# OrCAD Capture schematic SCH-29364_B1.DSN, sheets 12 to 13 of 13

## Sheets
12 X-02 IOMUX
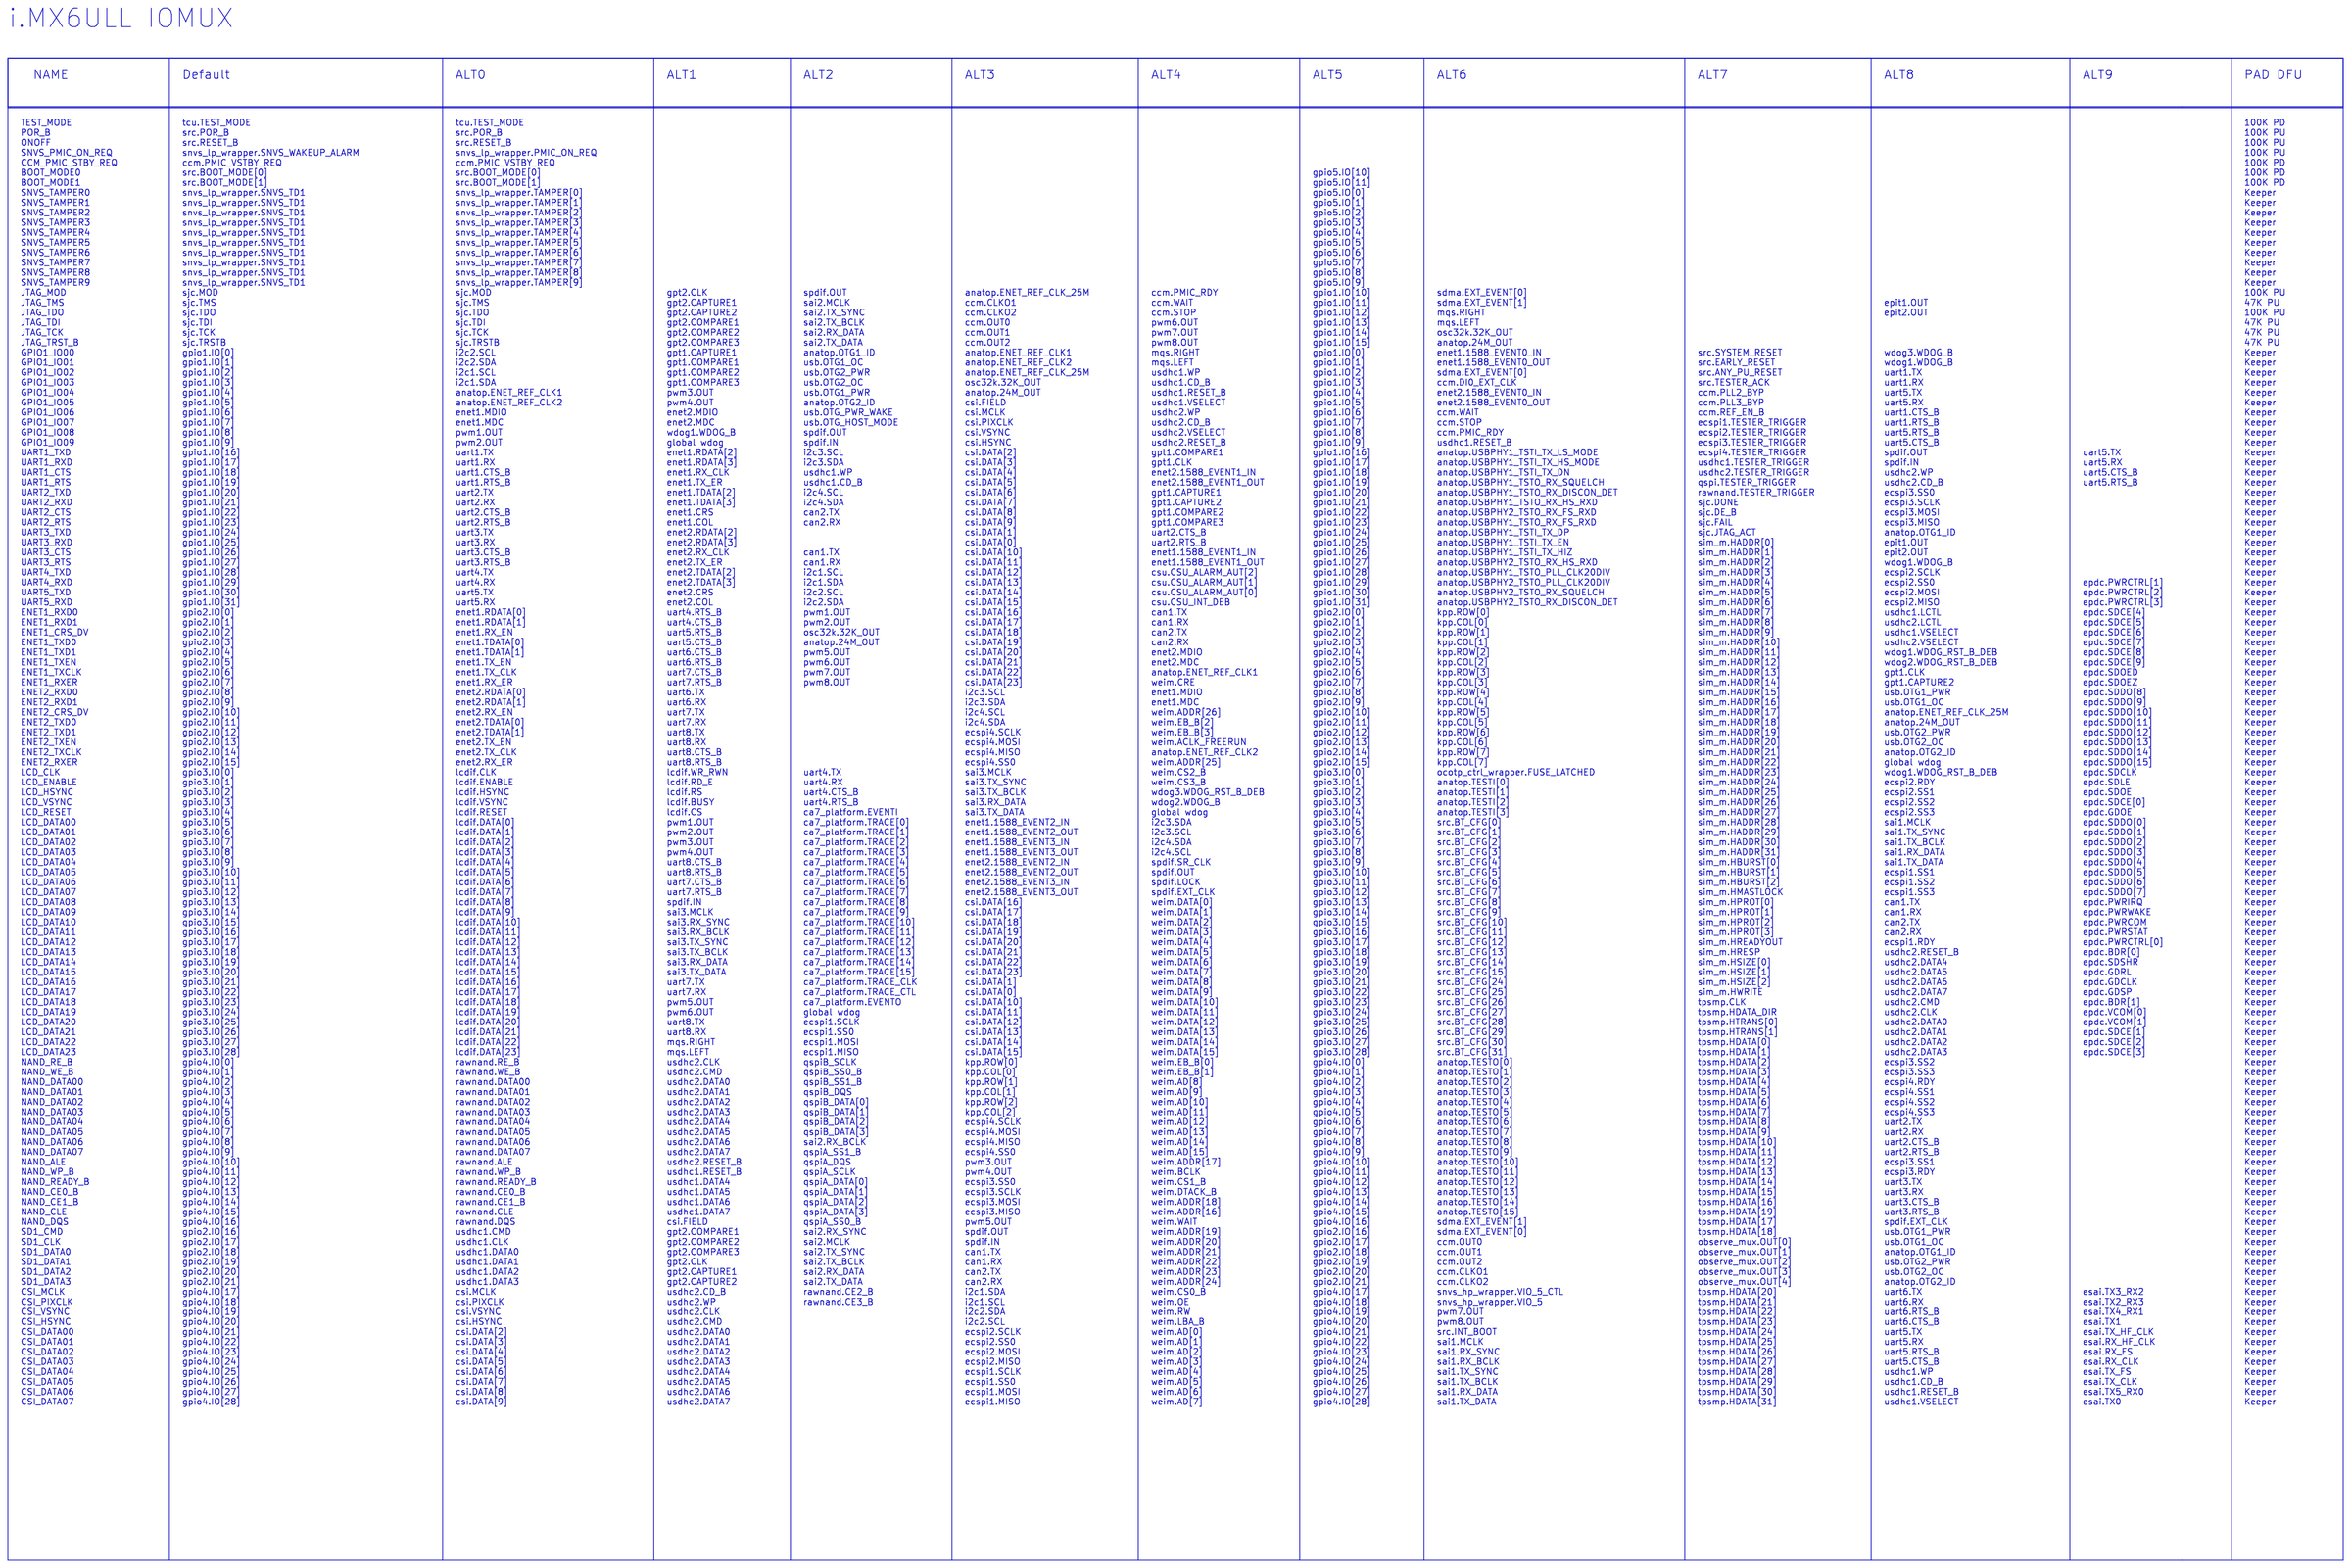
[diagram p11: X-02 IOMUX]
13 C-03 eMMC/NAND/TF/QSPI: size C
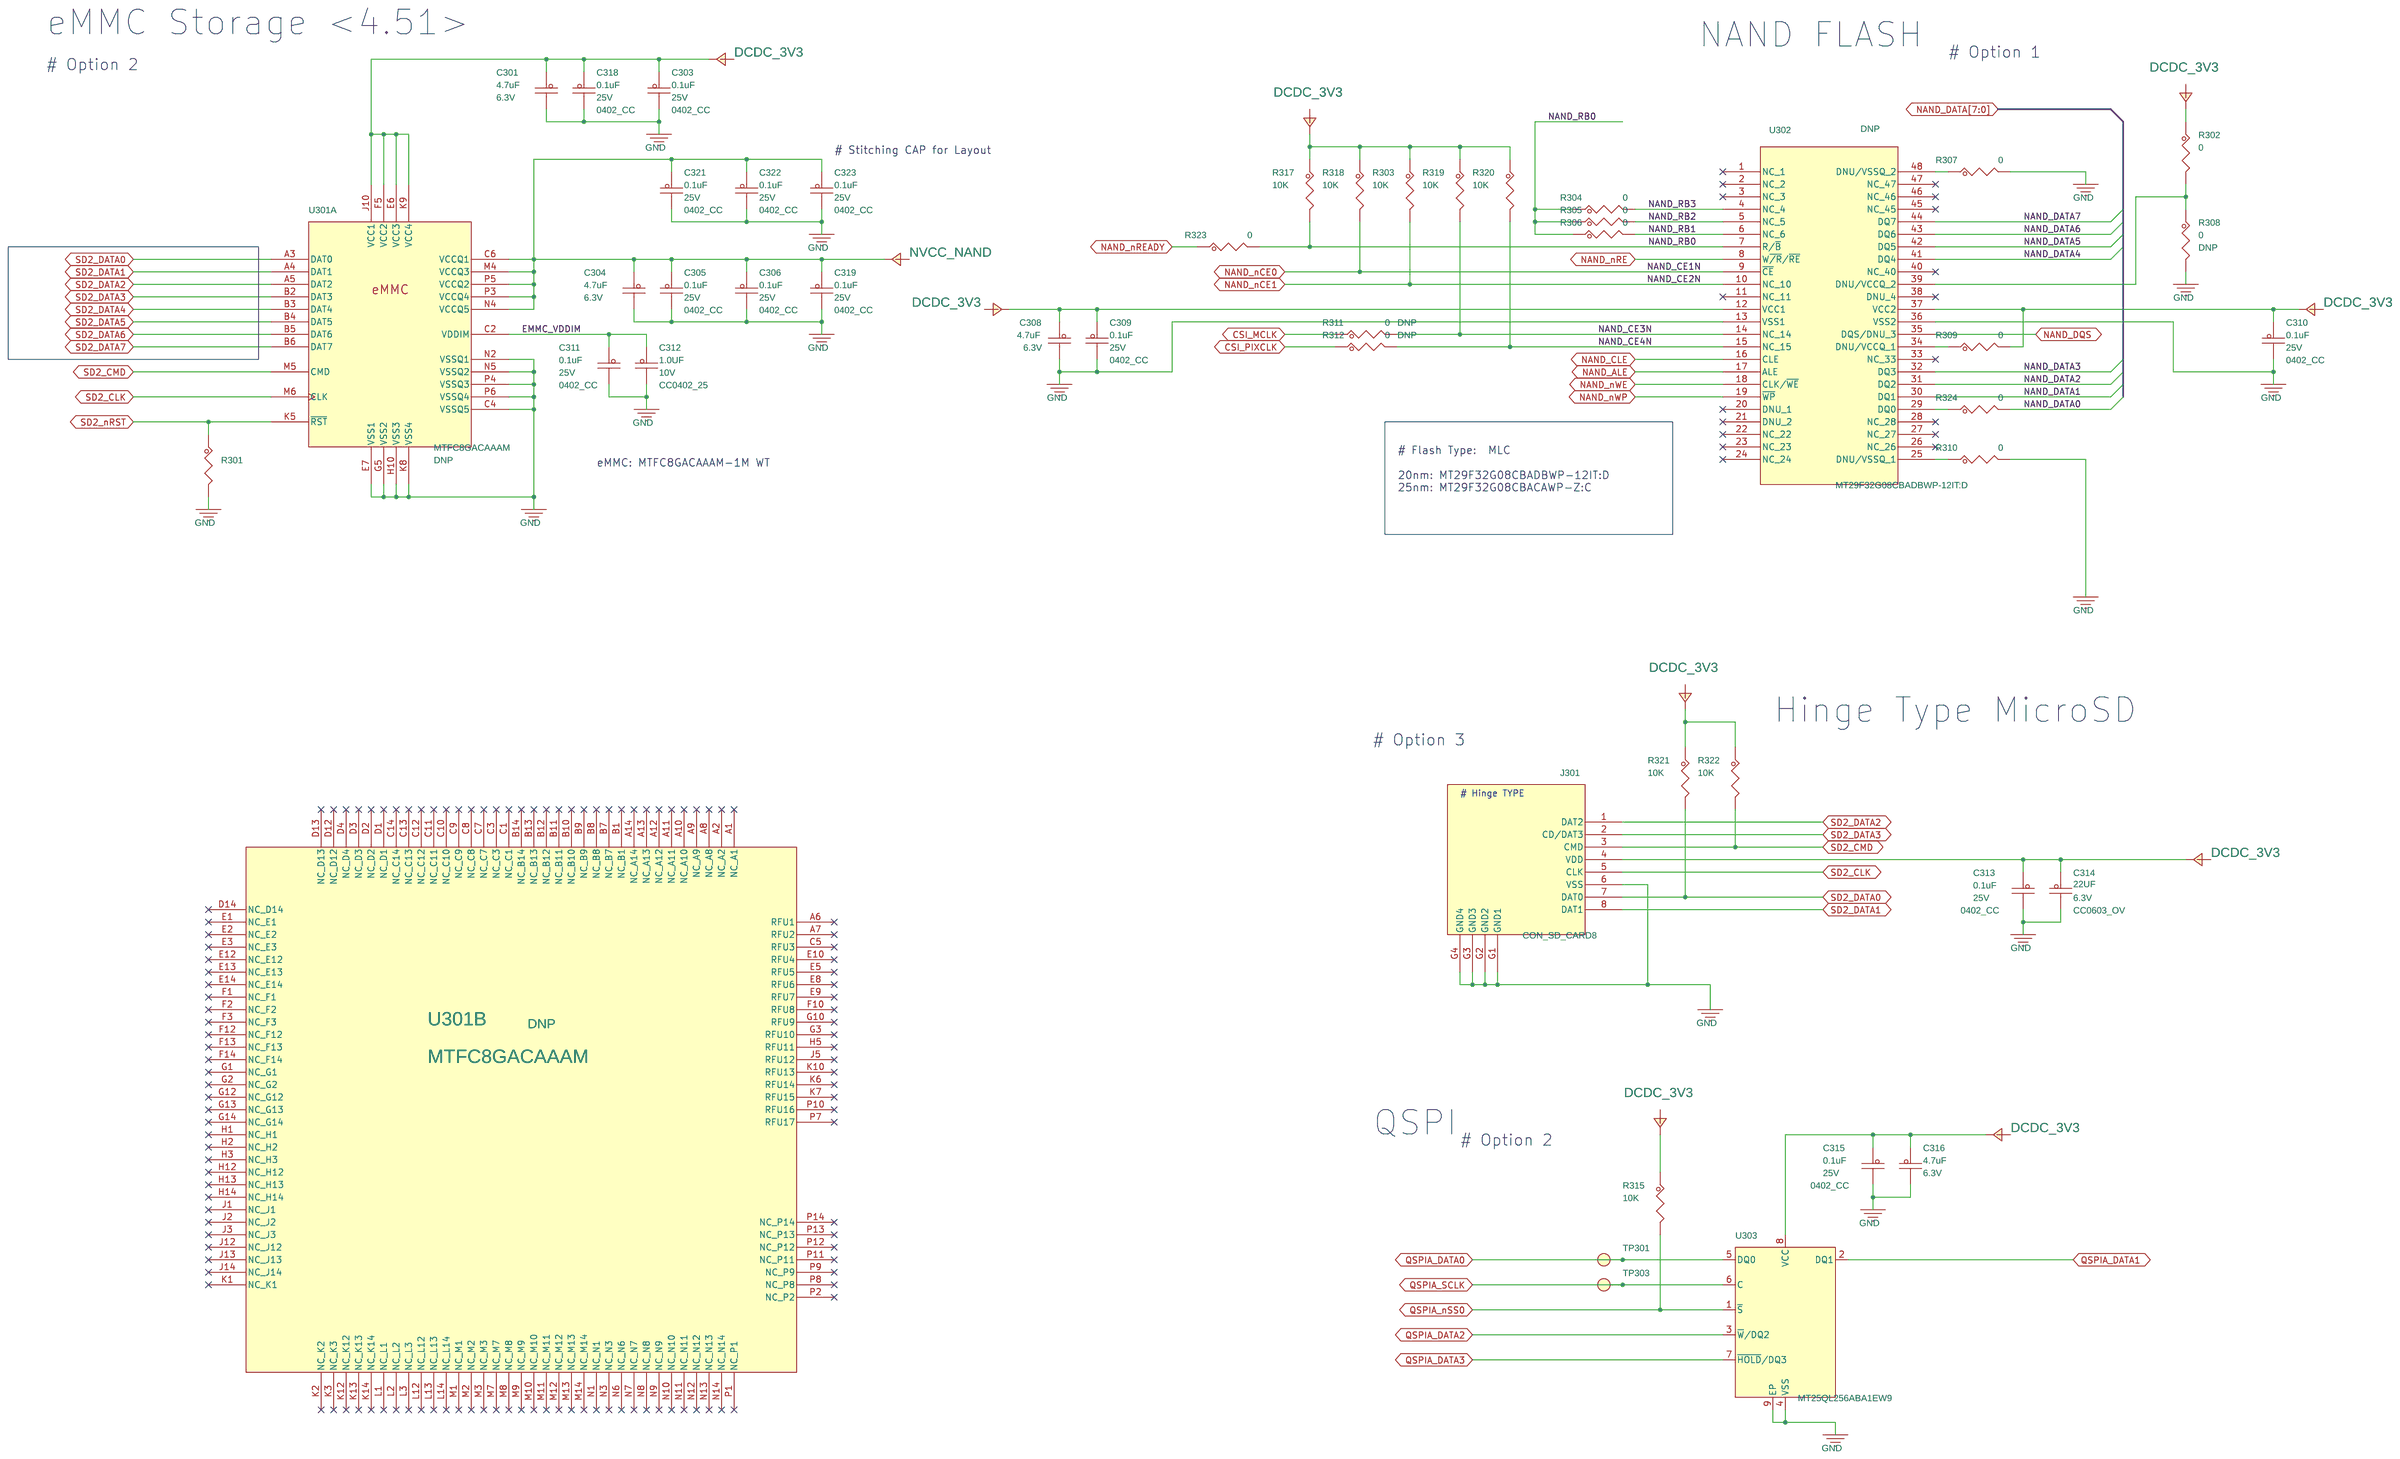
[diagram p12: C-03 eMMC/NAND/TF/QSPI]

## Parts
C301  4.7uF  [cc0402_tol0p15]
C303  0.1uF  [0402_CC]
C304  4.7uF  [cc0402_tol0p15]
C305  0.1uF  [0402_CC]
C306  0.1uF  [0402_CC]
C308  4.7uF  [cc0402_tol0p15]
C309  0.1uF  [0402_CC]
C310  0.1uF  [0402_CC]
C311  0.1uF  [0402_CC]
C312  1.0UF  [CC0402_25]
C313  0.1uF  [0402_CC]
C314  22UF  [CC0603_OV]
C315  0.1uF  [0402_CC]
C316  4.7uF  [cc0402_tol0p15]
C318  0.1uF  [0402_CC]
C319  0.1uF  [0402_CC]
C321  0.1uF  [0402_CC]
C322  0.1uF  [0402_CC]
C323  0.1uF  [0402_CC]
J301  CON_SD_CARD8  [con8_microsd_1p1_smt]
R301  10K  [0402_CC]
R302  0  [0402_CC]
R303  10K  [0402_CC]
R304  0  [0402_CC]
R305  0  [0402_CC]
R306  0  [0402_CC]
R307  0  [0402_CC]
R308  0  [0402_CC]
R309  0  [0402_CC]
R310  0  [0402_CC]
R311  0  [0402_CC]
R312  0  [0402_CC]
R315  10K  [0402_CC]
R317  10K  [0402_CC]
R318  10K  [0402_CC]
R319  10K  [0402_CC]
R320  10K  [0402_CC]
R321  10K  [0402_CC]
R322  10K  [0402_CC]
R323  0  [0402_CC]
R324  0  [0402_CC]
TP301  TP_35MIL  [testpoint_35mil]
TP303  TP_35MIL  [testpoint_35mil]
U301  MTFC8GACAAAM  [FBGA153_0P5_11P5X13]  (sections A,B)
U302  MT29F32G08CBADBWP-12IT:D  [tsop48_12x20]
U303  MT25QL256ABA1EW9  [wpdfn8_1p27_8x6mm]

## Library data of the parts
C301 C304 C308 C316 = CAP_NP: CAP CER 4.7UF 6.3V 20% X5R 0402; AGILE_PN: 150-78463; CAD_APPROVED: Yes; FPLIST: CC0402_25,CC0402_HD,0402_CC; HEIGHT: 0.65MM; MFG_NAME01: TDK; MFG_PN01: C1005X5R0J475M; ROHS: Yes; Rated Voltage: 6.3V; Temp Range: -55C to +85C; Tolerance: 20%; VOLTAGE: 6.3V; voltage rating: 6.3V
C303 C305 C306 C309-C311 C313 C315 C318 C319 C321-C323 = CAP_NP: CAP CER 0.1UF 25V 10% X5R 0402; AGILE_PN: 150-78633; CAD_APPROVED: Yes; FPLIST: CC0402_25,CC0402_HD,0402_CC; HEIGHT: 0.55MM; MFG_NAME01: YAGEO AMERICA; MFG_PN01: CC0402KRX5R8BB104; Package Size: 0402; ROHS: Yes; Rated Voltage: 25V; Temp Range: -55C to +85C; Tolerance: 10%; VOLTAGE: 25V
C312 = CAP_NP: CAP CER 1.0UF 10V 10% X5R 0402; AGILE_PN: 150-75772; CAD_APPROVED: Yes; FPLIST: CC0402_25,CC0402_HD,0402_CC; HEIGHT: 0.6MM; MFG_NAME01: YAGEO AMERICA; MFG_PN01: CC0402KRX5R6BB105; Package Size: 0402; ROHS: Yes; Rated Voltage: 10V; Temp Range: -55C to +85C; Tolerance: 10%; VOLTAGE: 10V
C314 = CAP_NP: CAP CER 22UF 6.3V 20% X5R 0603; AGILE_PN: 150-78467; CAD_APPROVED: Yes; FPLIST: CC0603_OV,CC0603,0603_CC; HEIGHT: 1MM; MFG_NAME01: SAMSUNG; MFG_PN01: CL10A226MQ8NRNE; Package Size: 0603; ROHS: Yes; Rated Voltage: 6.3V; Temp Range: -55C to +85C; Tolerance: 20%; VOLTAGE: 6.3V; voltage rating: 6.3V
J301 = CON_MICROSD_8P_4G: CON 8 MICRO SD CARD HINGED TYPE SMT 1.1MM SP 81H AU; 3D_Mechanical_Footprint_File: http://fcl.am.freescale.net/ALLEGRO/step/con8_microsd_1p1_smt.STEP; AGILE_PN: 211-81952; CAD_APPROVED: Yes; Contact Voltage: 100 V DC; HEIGHT: 2.05MM; MFG_NAME01: MOLEX; MFG_PN01: 472192001; Package Type: SMD/SMT; ROHS: Yes; Temp Range: -40°C to +85°C
R301 = RES: RES MF 10K 1/16W 5% 0402; AGILE_PN: 470-75557; CAD_APPROVED: Yes; FPLIST: RC0402_25,RC0402_HD,0402_CC; HEIGHT: 0.4 MM; MFG_NAME01: BOURNS; MFG_PN01: CR0402-JW-103GLF; ROHS: Yes; TOL: 5%; Tolerance: 5%
R302 R304-R307 R309 R310 R323 R324 = RES: RES MF ZERO OHM 1/16W 5% 0402; AGILE_PN: 470-75394; CAD_APPROVED: Yes; FPLIST: RC0402_25,RC0402_HD,RC0402_X2,0402_CC; HEIGHT: 0.45 MM; MFG_NAME01: YAGEO AMERICA; MFG_PN01: RC0402JR-070RL; ROHS: Yes; Temp Range: -55 to +155C; Tolerance: 5%
R303 R315 R317-R322 = RES: RES MF 10K 1/16W 5% 0402; AGILE_PN: 470-75557; CAD_APPROVED: Yes; FPLIST: RC0402_25,RC0402_HD,0402_CC; HEIGHT: 0.4 MM; MFG_NAME01: BOURNS; MFG_PN01: CR0402-JW-103GLF; ROHS: Yes; Tolerance: 5%
R308 R311 R312 = RES: RES MF ZERO OHM 1/16W 5% 0402; AGILE_PN: 470-75394; ASSY_OPT: DNP; CAD_APPROVED: Yes; FPLIST: RC0402_25,RC0402_HD,RC0402_X2,0402_CC; HEIGHT: 0.45 MM; MFG_NAME01: YAGEO AMERICA; MFG_PN01: RC0402JR-070RL; ROHS: Yes; Temp Range: -55 to +155C; Tolerance: 5%
TP301 TP303 = T_POINT_R: TEST POINT PAD .035 SMT, no part to order; AGILE_PN: 510-75618; CAD_APPROVED: Yes; HEIGHT: 0.1MM; ROHS: Yes
U301 = MTFC4GMVEA_WFBGA_153P: IC MEM NAND FLASH 8GB MMC 4.51 CTLR 2.7-3.6V FBGA153; AGILE_PN: 342-00603; ASSY_OPT: DNP; CAD_APPROVED: Yes; HEIGHT: 1.165 MM; MFG_NAME01: MICRON; MFG_PN01: MTFC8GACAAAM-1M WT; ROHS: Yes; VOLTAGE: 2.7¨C3.6V
U302 = MT29F32G08CBADB_48P: OBSOLETE IC MEM NAND FLASH ASYNC 32GB 2.7-3.6V TSOP48. No Suggested Replacement.; AGILE_PN: 334-77617; ASSY_OPT: DNP; CAD_APPROVED: Yes; HEIGHT: 1.2 MM; MFG_NAME01: MICRON; ROHS: Yes; VOLTAGE: 2.7-3.6V
U303 = MT25QL256ABA1EW9_9P: IC MEM FLASH SERIAL NOR 256MBIT 2.7-3.6V MLP8; AGILE_PN: 334-77609; CAD_APPROVED: Yes; HEIGHT: 0.8MM; MFG_NAME01: MICRON; MFG_PN01: MT25QL256ABA1EW9-0SIT; ROHS: Yes; VOLTAGE: 2.7-3.6V

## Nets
GND: C301.2 C303.2 C304.2 C305.2 C306.2 C308.2 C309.2 C310.2 C311.2 C312.2 C313.2 C314.2 C315.2 C316.2 C318.2 C319.2 C321.2 C322.2 C323.2 J301.6(VSS) J301.G1(GND1) J301.G2(GND2) J301.G3(GND3) J301.G4(GND4) R301.2 R307.2 R308.2 R310.2 U301.C4(VSSQ5) U301.E7(VSS1) U301.G5(VSS2) U301.H10(VSS3) U301.K8(VSS4) U301.N2(VSSQ1) U301.N5(VSSQ2) U301.P4(VSSQ3) U301.P6(VSSQ4) U302.13(VSS1) U302.36(VSS2) U303.4(VSS) U303.9(EP) ; also on sheet 4 5 6 7 8 9 10
CSI_MCLK: R311.1 ; also on sheet 6 10
CSI_PIXCLK: R312.1 ; also on sheet 6 10
DCDC_3V3: C301.1 C303.1 C308.1 C309.1 C310.1 C313.1 C314.1 C315.1 C316.1 C318.1 J301.4(VDD) R302.1 R303.1 R309.2 R315.1 R317.1 R318.1 R319.1 R320.1 R321.1 R322.1 U301.E6(VCC3) U301.F5(VCC2) U301.J10(VCC1) U301.K9(VCC4) U302.12(VCC1) U302.37(VCC2) U303.8(VCC) ; also on sheet 6 7 8 9 10
EMMC_VDDIM: C311.1 C312.1 U301.C2(VDDIM)
NAND_ALE: R301.1 U301.K5(~{RST}) U302.17(ALE) ; also on sheet 6
NAND_CE3N: R311.2 R319.2 U302.14(NC)
NAND_CE4N: R312.2 R320.2 U302.15(NC)
NAND_CLE: U302.16(CLE) U303.7(~{HOLD}/DQ3) ; also on sheet 6
NAND_DATA0: J301.7(DAT0) R321.2 R324.2 U301.A3(DAT0) ; also on sheet 6
NAND_DATA1: J301.8(DAT1) U301.A4(DAT1) U302.30(DQ1) ; also on sheet 6
NAND_DATA2: J301.1(DAT2) U301.A5(DAT2) U302.31(DQ2) ; also on sheet 6
NAND_DATA3: J301.2(CD/DAT3) U301.B2(DAT3) U302.32(DQ3) ; also on sheet 6
NAND_DATA4: U301.B3(DAT4) U302.41(DQ4) ; also on sheet 6
NAND_DATA5: U301.B4(DAT5) U302.42(DQ5) ; also on sheet 6
NAND_DATA6: U301.B5(DAT6) U302.43(DQ6) ; also on sheet 6
NAND_DATA7: U301.B6(DAT7) U302.44(DQ7) ; also on sheet 6
NAND_DQS: R315.2 U302.35(DQS/DNU_3) U303.1(~{S}) ; also on sheet 6
NAND_nCE0: R318.2 U302.9(~{CE}) U303.2(DQ1) ; also on sheet 6
NAND_nCE1: R303.2 U302.10(NC) U303.3(~{W}/DQ2) ; also on sheet 6
NAND_nRE: J301.5(CLK) U301.M6(CLK) U302.8(W~{/R}/~{RE}) ; also on sheet 6
NAND_nREADY: R323.1 TP301.1(TP) U303.5(DQ0) ; also on sheet 6
NAND_nWE: J301.3(CMD) R322.2 U301.M5(CMD) U302.18(CLK/~{WE}) ; also on sheet 6
NAND_nWP: TP303.1(TP) U302.19(~{WP}) U303.6(C) ; also on sheet 6
NAND_RB0: R304.1 R305.1 R306.1 R317.2 R323.2 U302.7(R/~{B})
NAND_RB1: R306.2 U302.6(NC)
NAND_RB2: R305.2 U302.5(NC)
NAND_RB3: R304.2 U302.4(NC)
NVCC_NAND: C304.1 C305.1 C306.1 C319.1 C321.1 C322.1 C323.1 U301.C6(VCCQ1) U301.M4(VCCQ3) U301.N4(VCCQ5) U301.P3(VCCQ4) U301.P5(VCCQ2) ; also on sheet 6 9
N100071137: R307.1 U302.48(DNU/VSSQ_2)
N100071182: R302.2 R308.1 U302.39(DNU/VCCQ_2)
N100071695: R309.1 U302.34(DNU/VCCQ_1)
N100071844: R324.1 U302.29(DQ0)
N100071879: R310.1 U302.25(DNU/VSSQ_1)

Not connected (* = marked no-connect by the designer): U301 A1(NC)* A2(NC)* A6(RFU1)* A7(RFU2)* A8(NC)* A9(NC)* A10(NC)* A11(NC)* A12(NC)* A13(NC)* A14(NC)* B1(NC)* B7(NC)* B8(NC)* B9(NC)* B10(NC)* B11(NC)* B12(NC)* B13(NC)* B14(NC)* C1(NC)* C3(NC)* C5(RFU3)* C7(NC)* C8(NC)* C9(NC)* C10(NC)* C11(NC)* C12(NC)* C13(NC)* C14(NC)* D1(NC)* D2(NC)* D3(NC)* D4(NC)* D12(NC)* D13(NC)* D14(NC)* E1(NC)* E2(NC)* E3(NC)* E5(RFU5)* E8(RFU6)* E9(RFU7)* E10(RFU4)* E12(NC)* E13(NC)* E14(NC)* F1(NC)* F2(NC)* F3(NC)* F10(RFU8)* F12(NC)* F13(NC)* F14(NC)* G1(NC)* G2(NC)* G3(RFU10)* G10(RFU9)* G12(NC)* G13(NC)* G14(NC)* H1(NC)* H2(NC)* H3(NC)* H5(RFU11)* H12(NC)* H13(NC)* H14(NC)* J1(NC)* J2(NC)* J3(NC)* J5(RFU12)* J12(NC)* J13(NC)* J14(NC)* K1(NC)* K2(NC)* K3(NC)* K6(RFU14)* K7(RFU15)* K10(RFU13)* K12(NC)* K13(NC)* K14(NC)* L1(NC)* L2(NC)* L3(NC)* L12(NC)* L13(NC)* L14(NC)* M1(NC)* M2(NC)* M3(NC)* M7(NC)* M8(NC)* M9(NC)* M10(NC)* M11(NC)* M12(NC)* M13(NC)* M14(NC)* N1(NC)* N3(NC)* N6(NC)* N7(NC)* N8(NC)* N9(NC)* N10(NC)* N11(NC)* N12(NC)* N13(NC)* N14(NC)* P1(NC)* P2(NC)* P7(RFU17)* P8(NC)* P9(NC)* P10(RFU16)* P11(NC)* P12(NC)* P13(NC)* P14(NC)*; U302 1(NC)* 2(NC)* 3(NC)* 11(NC)* 20(DNU_1)* 21(DNU_2)* 22(NC)* 23(NC)* 24(NC)* 26(NC)* 27(NC)* 28(NC)* 33(NC)* 38(DNU_4)* 40(NC)* 45(NC)* 46(NC)* 47(NC)*

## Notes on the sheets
sheet 12
- i.MX6ULL IOMUX
- NAME
- Default
- ALT0
- ALT1
- ALT2
- ALT3
- ALT4
- ALT5
- ALT6
- ALT7
- ALT8
- ALT9
- PAD DFU
- TEST_MODE
  POR_B
  ONOFF
  SNVS_PMIC_ON_REQ
  CCM_PMIC_STBY_REQ
  BOOT_MODE0
  BOOT_MODE1
  SNVS_TAMPER0
  SNVS_TAMPER1
  SNVS_TAMPER2
  SNVS_TAMPER3
  SNVS_TAMPER4
  SNVS_TAMPER5
  SNVS_TAMPER6
  SNVS_TAMPER7
  SNVS_TAMPER8
  SNVS_TAMPER9
  JTAG_MOD
  JTAG_TMS
  JTAG_TDO
  JTAG_TDI
  JTAG_TCK
  JTAG_TRST_B
  GPIO1_IO00
  GPIO1_IO01
  GPIO1_IO02
  GPIO1_IO03
  GPIO1_IO04
  GPIO1_IO05
  GPIO1_IO06
  GPIO1_IO07
  GPIO1_IO08
  GPIO1_IO09
  UART1_TXD
  UART1_RXD
  UART1_CTS
  UART1_RTS
  UART2_TXD
  UART2_RXD
  UART2_CTS
  UART2_RTS
  UART3_TXD
  UART3_RXD
  UART3_CTS
  UART3_RTS
  UART4_TXD
  UART4_RXD
  UART5_TXD
  UART5_RXD
  ENET1_RXD0
  ENET1_RXD1
  ENET1_CRS_DV
  ENET1_TXD0
  ENET1_TXD1
  ENET1_TXEN
  ENET1_TXCLK
  ENET1_RXER
  ENET2_RXD0
  ENET2_RXD1
  ENET2_CRS_DV
  ENET2_TXD0
  ENET2_TXD1
  ENET2_TXEN
  ENET2_TXCLK
  ENET2_RXER
  LCD_CLK
  LCD_ENABLE
  LCD_HSYNC
  LCD_VSYNC
  LCD_RESET
  LCD_DATA00
  LCD_DATA01
  LCD_DATA02
  LCD_DATA03
  LCD_DATA04
  LCD_DATA05
  LCD_DATA06
  LCD_DATA07
  LCD_DATA08
  LCD_DATA09
  LCD_DATA10
  LCD_DATA11
  LCD_DATA12
  LCD_DATA13
  LCD_DATA14
  LCD_DATA15
  LCD_DATA16
  LCD_DATA17
  LCD_DATA18
  LCD_DATA19
  LCD_DATA20
  LCD_DATA21
  LCD_DATA22
  LCD_DATA23
  NAND_RE_B
  NAND_WE_B
  NAND_DATA00
  NAND_DATA01
  NAND_DATA02
  NAND_DATA03
  NAND_DATA04
  NAND_DATA05
  NAND_DATA06
  NAND_DATA07
  NAND_ALE
  NAND_WP_B
  NAND_READY_B
  NAND_CE0_B
  NAND_CE1_B
  NAND_CLE
  NAND_DQS
  SD1_CMD
  SD1_CLK
  SD1_DATA0
  SD1_DATA1
  SD1_DATA2
  SD1_DATA3
  CSI_MCLK
  CSI_PIXCLK
  CSI_VSYNC
  CSI_HSYNC
  CSI_DATA00
  CSI_DATA01
  CSI_DATA02
  CSI_DATA03
  CSI_DATA04
  CSI_DATA05
  CSI_DATA06
  CSI_DATA07
- tcu.TEST_MODE
  src.POR_B
  src.RESET_B
  snvs_lp_wrapper.SNVS_WAKEUP_ALARM
  ccm.PMIC_VSTBY_REQ
  src.BOOT_MODE[0]
  src.BOOT_MODE[1]
  snvs_lp_wrapper.SNVS_TD1
  snvs_lp_wrapper.SNVS_TD1
  snvs_lp_wrapper.SNVS_TD1
  snvs_lp_wrapper.SNVS_TD1
  snvs_lp_wrapper.SNVS_TD1
  snvs_lp_wrapper.SNVS_TD1
  snvs_lp_wrapper.SNVS_TD1
  snvs_lp_wrapper.SNVS_TD1
  snvs_lp_wrapper.SNVS_TD1
  snvs_lp_wrapper.SNVS_TD1
  sjc.MOD
  sjc.TMS
  sjc.TDO
  sjc.TDI
  sjc.TCK
  sjc.TRSTB
  gpio1.IO[0]
  gpio1.IO[1]
  gpio1.IO[2]
  gpio1.IO[3]
  gpio1.IO[4]
  gpio1.IO[5]
  gpio1.IO[6]
  gpio1.IO[7]
  gpio1.IO[8]
  gpio1.IO[9]
  gpio1.IO[16]
  gpio1.IO[17]
  gpio1.IO[18]
  gpio1.IO[19]
  gpio1.IO[20]
  gpio1.IO[21]
  gpio1.IO[22]
  gpio1.IO[23]
  gpio1.IO[24]
  gpio1.IO[25]
  gpio1.IO[26]
  gpio1.IO[27]
  gpio1.IO[28]
  gpio1.IO[29]
  gpio1.IO[30]
  gpio1.IO[31]
  gpio2.IO[0]
  gpio2.IO[1]
  gpio2.IO[2]
  gpio2.IO[3]
  gpio2.IO[4]
  gpio2.IO[5]
  gpio2.IO[6]
  gpio2.IO[7]
  gpio2.IO[8]
  gpio2.IO[9]
  gpio2.IO[10]
  gpio2.IO[11]
  gpio2.IO[12]
  gpio2.IO[13]
  gpio2.IO[14]
  gpio2.IO[15]
  gpio3.IO[0]
  gpio3.IO[1]
  gpio3.IO[2]
  gpio3.IO[3]
  gpio3.IO[4]
  gpio3.IO[5]
  gpio3.IO[6]
  gpio3.IO[7]
  gpio3.IO[8]
  gpio3.IO[9]
  gpio3.IO[10]
  gpio3.IO[11]
  gpio3.IO[12]
  gpio3.IO[13]
  gpio3.IO[14]
  gpio3.IO[15]
  gpio3.IO[16]
  gpio3.IO[17]
  gpio3.IO[18]
  gpio3.IO[19]
  gpio3.IO[20]
  gpio3.IO[21]
  gpio3.IO[22]
  gpio3.IO[23]
  gpio3.IO[24]
  gpio3.IO[25]
  gpio3.IO[26]
  gpio3.IO[27]
  gpio3.IO[28]
  gpio4.IO[0]
  gpio4.IO[1]
  gpio4.IO[2]
  gpio4.IO[3]
  gpio4.IO[4]
  gpio4.IO[5]
  gpio4.IO[6]
  gpio4.IO[7]
  gpio4.IO[8]
  gpio4.IO[9]
  gpio4.IO[10]
  gpio4.IO[11]
  gpio4.IO[12]
  gpio4.IO[13]
  gpio4.IO[14]
  gpio4.IO[15]
  gpio4.IO[16]
  gpio2.IO[16]
  gpio2.IO[17]
  gpio2.IO[18]
  gpio2.IO[19]
  gpio2.IO[20]
  gpio2.IO[21]
  gpio4.IO[17]
  gpio4.IO[18]
  gpio4.IO[19]
  gpio4.IO[20]
  gpio4.IO[21]
  gpio4.IO[22]
  gpio4.IO[23]
  gpio4.IO[24]
  gpio4.IO[25]
  gpio4.IO[26]
  gpio4.IO[27]
  gpio4.IO[28]
- tcu.TEST_MODE
  src.POR_B
  src.RESET_B
  snvs_lp_wrapper.PMIC_ON_REQ
  ccm.PMIC_VSTBY_REQ
  src.BOOT_MODE[0]
  src.BOOT_MODE[1]
  snvs_lp_wrapper.TAMPER[0]
  snvs_lp_wrapper.TAMPER[1]
  snvs_lp_wrapper.TAMPER[2]
  snvs_lp_wrapper.TAMPER[3]
  snvs_lp_wrapper.TAMPER[4]
  snvs_lp_wrapper.TAMPER[5]
  snvs_lp_wrapper.TAMPER[6]
  snvs_lp_wrapper.TAMPER[7]
  snvs_lp_wrapper.TAMPER[8]
  snvs_lp_wrapper.TAMPER[9]
  sjc.MOD
  sjc.TMS
  sjc.TDO
  sjc.TDI
  sjc.TCK
  sjc.TRSTB
  i2c2.SCL
  i2c2.SDA
  i2c1.SCL
  i2c1.SDA
  anatop.ENET_REF_CLK1
  anatop.ENET_REF_CLK2
  enet1.MDIO
  enet1.MDC
  pwm1.OUT
  pwm2.OUT
  uart1.TX
  uart1.RX
  uart1.CTS_B
  uart1.RTS_B
  uart2.TX
  uart2.RX
  uart2.CTS_B
  uart2.RTS_B
  uart3.TX
  uart3.RX
  uart3.CTS_B
  uart3.RTS_B
  uart4.TX
  uart4.RX
  uart5.TX
  uart5.RX
  enet1.RDATA[0]
  enet1.RDATA[1]
  enet1.RX_EN
  enet1.TDATA[0]
  enet1.TDATA[1]
  enet1.TX_EN
  enet1.TX_CLK
  enet1.RX_ER
  enet2.RDATA[0]
  enet2.RDATA[1]
  enet2.RX_EN
  enet2.TDATA[0]
  enet2.TDATA[1]
  enet2.TX_EN
  enet2.TX_CLK
  enet2.RX_ER
  lcdif.CLK
  lcdif.ENABLE
  lcdif.HSYNC
  lcdif.VSYNC
  lcdif.RESET
  lcdif.DATA[0]
  lcdif.DATA[1]
  lcdif.DATA[2]
  lcdif.DATA[3]
  lcdif.DATA[4]
  lcdif.DATA[5]
  lcdif.DATA[6]
  lcdif.DATA[7]
  lcdif.DATA[8]
  lcdif.DATA[9]
  lcdif.DATA[10]
  lcdif.DATA[11]
  lcdif.DATA[12]
  lcdif.DATA[13]
  lcdif.DATA[14]
  lcdif.DATA[15]
  lcdif.DATA[16]
  lcdif.DATA[17]
  lcdif.DATA[18]
  lcdif.DATA[19]
  lcdif.DATA[20]
  lcdif.DATA[21]
  lcdif.DATA[22]
  lcdif.DATA[23]
  rawnand.RE_B
  rawnand.WE_B
  rawnand.DATA00
  rawnand.DATA01
  rawnand.DATA02
  rawnand.DATA03
  rawnand.DATA04
  rawnand.DATA05
  rawnand.DATA06
  rawnand.DATA07
  rawnand.ALE
  rawnand.WP_B
  rawnand.READY_B
  rawnand.CE0_B
  rawnand.CE1_B
  rawnand.CLE
  rawnand.DQS
  usdhc1.CMD
  usdhc1.CLK
  usdhc1.DATA0
  usdhc1.DATA1
  usdhc1.DATA2
  usdhc1.DATA3
  csi.MCLK
  csi.PIXCLK
  csi.VSYNC
  csi.HSYNC
  csi.DATA[2]
  csi.DATA[3]
  csi.DATA[4]
  csi.DATA[5]
  csi.DATA[6]
  csi.DATA[7]
  csi.DATA[8]
  csi.DATA[9]
- gpt2.CLK
  gpt2.CAPTURE1
  gpt2.CAPTURE2
  gpt2.COMPARE1
  gpt2.COMPARE2
  gpt2.COMPARE3
  gpt1.CAPTURE1
  gpt1.COMPARE1
  gpt1.COMPARE2
  gpt1.COMPARE3
  pwm3.OUT
  pwm4.OUT
  enet2.MDIO
  enet2.MDC
  wdog1.WDOG_B
  global wdog
  enet1.RDATA[2]
  enet1.RDATA[3]
  enet1.RX_CLK
  enet1.TX_ER
  enet1.TDATA[2]
  enet1.TDATA[3]
  enet1.CRS
  enet1.COL
  enet2.RDATA[2]
  enet2.RDATA[3]
  enet2.RX_CLK
  enet2.TX_ER
  enet2.TDATA[2]
  enet2.TDATA[3]
  enet2.CRS
  enet2.COL
  uart4.RTS_B
  uart4.CTS_B
  uart5.RTS_B
  uart5.CTS_B
  uart6.CTS_B
  uart6.RTS_B
  uart7.CTS_B
  uart7.RTS_B
  uart6.TX
  uart6.RX
  uart7.TX
  uart7.RX
  uart8.TX
  uart8.RX
  uart8.CTS_B
  uart8.RTS_B
  lcdif.WR_RWN
  lcdif.RD_E
  lcdif.RS
  lcdif.BUSY
  lcdif.CS
  pwm1.OUT
  pwm2.OUT
  pwm3.OUT
  pwm4.OUT
  uart8.CTS_B
  uart8.RTS_B
  uart7.CTS_B
  uart7.RTS_B
  spdif.IN
  sai3.MCLK
  sai3.RX_SYNC
  sai3.RX_BCLK
  sai3.TX_SYNC
  sai3.TX_BCLK
  sai3.RX_DATA
  sai3.TX_DATA
  uart7.TX
  uart7.RX
  pwm5.OUT
  pwm6.OUT
  uart8.TX
  uart8.RX
  mqs.RIGHT
  mqs.LEFT
  usdhc2.CLK
  usdhc2.CMD
  usdhc2.DATA0
  usdhc2.DATA1
  usdhc2.DATA2
  usdhc2.DATA3
  usdhc2.DATA4
  usdhc2.DATA5
  usdhc2.DATA6
  usdhc2.DATA7
  usdhc2.RESET_B
  usdhc1.RESET_B
  usdhc1.DATA4
  usdhc1.DATA5
  usdhc1.DATA6
  usdhc1.DATA7
  csi.FIELD
  gpt2.COMPARE1
  gpt2.COMPARE2
  gpt2.COMPARE3
  gpt2.CLK
  gpt2.CAPTURE1
  gpt2.CAPTURE2
  usdhc2.CD_B
  usdhc2.WP
  usdhc2.CLK
  usdhc2.CMD
  usdhc2.DATA0
  usdhc2.DATA1
  usdhc2.DATA2
  usdhc2.DATA3
  usdhc2.DATA4
  usdhc2.DATA5
  usdhc2.DATA6
  usdhc2.DATA7
- spdif.OUT
  sai2.MCLK
  sai2.TX_SYNC
  sai2.TX_BCLK
  sai2.RX_DATA
  sai2.TX_DATA
  anatop.OTG1_ID
  usb.OTG1_OC
  usb.OTG2_PWR
  usb.OTG2_OC
  usb.OTG1_PWR
  anatop.OTG2_ID
  usb.OTG_PWR_WAKE
  usb.OTG_HOST_MODE
  spdif.OUT
  spdif.IN
  i2c3.SCL
  i2c3.SDA
  usdhc1.WP
  usdhc1.CD_B
  i2c4.SCL
  i2c4.SDA
  can2.TX
  can2.RX
  can1.TX
  can1.RX
  i2c1.SCL
  i2c1.SDA
  i2c2.SCL
  i2c2.SDA
  pwm1.OUT
  pwm2.OUT
  osc32k.32K_OUT
  anatop.24M_OUT
  pwm5.OUT
  pwm6.OUT
  pwm7.OUT
  pwm8.OUT
  uart4.TX
  uart4.RX
  uart4.CTS_B
  uart4.RTS_B
  ca7_platform.EVENTI
  ca7_platform.TRACE[0]
  ca7_platform.TRACE[1]
  ca7_platform.TRACE[2]
  ca7_platform.TRACE[3]
  ca7_platform.TRACE[4]
  ca7_platform.TRACE[5]
  ca7_platform.TRACE[6]
  ca7_platform.TRACE[7]
  ca7_platform.TRACE[8]
  ca7_platform.TRACE[9]
  ca7_platform.TRACE[10]
  ca7_platform.TRACE[11]
  ca7_platform.TRACE[12]
  ca7_platform.TRACE[13]
  ca7_platform.TRACE[14]
  ca7_platform.TRACE[15]
  ca7_platform.TRACE_CLK
  ca7_platform.TRACE_CTL
  ca7_platform.EVENTO
  global wdog
  ecspi1.SCLK
  ecspi1.SS0
  ecspi1.MOSI
  ecspi1.MISO
  qspiB_SCLK
  qspiB_SS0_B
  qspiB_SS1_B
  qspiB_DQS
  qspiB_DATA[0]
  qspiB_DATA[1]
  qspiB_DATA[2]
  qspiB_DATA[3]
  sai2.RX_BCLK
  qspiA_SS1_B
  qspiA_DQS
  qspiA_SCLK
  qspiA_DATA[0]
  qspiA_DATA[1]
  qspiA_DATA[2]
  qspiA_DATA[3]
  qspiA_SS0_B
  sai2.RX_SYNC
  sai2.MCLK
  sai2.TX_SYNC
  sai2.TX_BCLK
  sai2.RX_DATA
  sai2.TX_DATA
  rawnand.CE2_B
  rawnand.CE3_B
- anatop.ENET_REF_CLK_25M
  ccm.CLKO1
  ccm.CLKO2
  ccm.OUT0
  ccm.OUT1
  ccm.OUT2
  anatop.ENET_REF_CLK1
  anatop.ENET_REF_CLK2
  anatop.ENET_REF_CLK_25M
  osc32k.32K_OUT
  anatop.24M_OUT
  csi.FIELD
  csi.MCLK
  csi.PIXCLK
  csi.VSYNC
  csi.HSYNC
  csi.DATA[2]
  csi.DATA[3]
  csi.DATA[4]
  csi.DATA[5]
  csi.DATA[6]
  csi.DATA[7]
  csi.DATA[8]
  csi.DATA[9]
  csi.DATA[1]
  csi.DATA[0]
  csi.DATA[10]
  csi.DATA[11]
  csi.DATA[12]
  csi.DATA[13]
  csi.DATA[14]
  csi.DATA[15]
  csi.DATA[16]
  csi.DATA[17]
  csi.DATA[18]
  csi.DATA[19]
  csi.DATA[20]
  csi.DATA[21]
  csi.DATA[22]
  csi.DATA[23]
  i2c3.SCL
  i2c3.SDA
  i2c4.SCL
  i2c4.SDA
  ecspi4.SCLK
  ecspi4.MOSI
  ecspi4.MISO
  ecspi4.SS0
  sai3.MCLK
  sai3.TX_SYNC
  sai3.TX_BCLK
  sai3.RX_DATA
  sai3.TX_DATA
  enet1.1588_EVENT2_IN
  enet1.1588_EVENT2_OUT
  enet1.1588_EVENT3_IN
  enet1.1588_EVENT3_OUT
  enet2.1588_EVENT2_IN
  enet2.1588_EVENT2_OUT
  enet2.1588_EVENT3_IN
  enet2.1588_EVENT3_OUT
  csi.DATA[16]
  csi.DATA[17]
  csi.DATA[18]
  csi.DATA[19]
  csi.DATA[20]
  csi.DATA[21]
  csi.DATA[22]
  csi.DATA[23]
  csi.DATA[1]
  csi.DATA[0]
  csi.DATA[10]
  csi.DATA[11]
  csi.DATA[12]
  csi.DATA[13]
  csi.DATA[14]
  csi.DATA[15]
  kpp.ROW[0]
  kpp.COL[0]
  kpp.ROW[1]
  kpp.COL[1]
  kpp.ROW[2]
  kpp.COL[2]
  ecspi4.SCLK
  ecspi4.MOSI
  ecspi4.MISO
  ecspi4.SS0
  pwm3.OUT
  pwm4.OUT
  ecspi3.SS0
  ecspi3.SCLK
  ecspi3.MOSI
  ecspi3.MISO
  pwm5.OUT
  spdif.OUT
  spdif.IN
  can1.TX
  can1.RX
  can2.TX
  can2.RX
  i2c1.SDA
  i2c1.SCL
  i2c2.SDA
  i2c2.SCL
  ecspi2.SCLK
  ecspi2.SS0
  ecspi2.MOSI
  ecspi2.MISO
  ecspi1.SCLK
  ecspi1.SS0
  ecspi1.MOSI
  ecspi1.MISO
- ccm.PMIC_RDY
  ccm.WAIT
  ccm.STOP
  pwm6.OUT
  pwm7.OUT
  pwm8.OUT
  mqs.RIGHT
  mqs.LEFT
  usdhc1.WP
  usdhc1.CD_B
  usdhc1.RESET_B
  usdhc1.VSELECT
  usdhc2.WP
  usdhc2.CD_B
  usdhc2.VSELECT
  usdhc2.RESET_B
  gpt1.COMPARE1
  gpt1.CLK
  enet2.1588_EVENT1_IN
  enet2.1588_EVENT1_OUT
  gpt1.CAPTURE1
  gpt1.CAPTURE2
  gpt1.COMPARE2
  gpt1.COMPARE3
  uart2.CTS_B
  uart2.RTS_B
  enet1.1588_EVENT1_IN
  enet1.1588_EVENT1_OUT
  csu.CSU_ALARM_AUT[2]
  csu.CSU_ALARM_AUT[1]
  csu.CSU_ALARM_AUT[0]
  csu.CSU_INT_DEB
  can1.TX
  can1.RX
  can2.TX
  can2.RX
  enet2.MDIO
  enet2.MDC
  anatop.ENET_REF_CLK1
  weim.CRE
  enet1.MDIO
  enet1.MDC
  weim.ADDR[26]
  weim.EB_B[2]
  weim.EB_B[3]
  weim.ACLK_FREERUN
  anatop.ENET_REF_CLK2
  weim.ADDR[25]
  weim.CS2_B
  weim.CS3_B
  wdog3.WDOG_RST_B_DEB
  wdog2.WDOG_B
  global wdog
  i2c3.SDA
  i2c3.SCL
  i2c4.SDA
  i2c4.SCL
  spdif.SR_CLK
  spdif.OUT
  spdif.LOCK
  spdif.EXT_CLK
  weim.DATA[0]
  weim.DATA[1]
  weim.DATA[2]
  weim.DATA[3]
  weim.DATA[4]
  weim.DATA[5]
  weim.DATA[6]
  weim.DATA[7]
  weim.DATA[8]
  weim.DATA[9]
  weim.DATA[10]
  weim.DATA[11]
  weim.DATA[12]
  weim.DATA[13]
  weim.DATA[14]
  weim.DATA[15]
  weim.EB_B[0]
  weim.EB_B[1]
  weim.AD[8]
  weim.AD[9]
  weim.AD[10]
  weim.AD[11]
  weim.AD[12]
  weim.AD[13]
  weim.AD[14]
  weim.AD[15]
  weim.ADDR[17]
  weim.BCLK
  weim.CS1_B
  weim.DTACK_B
  weim.ADDR[18]
  weim.ADDR[16]
  weim.WAIT
  weim.ADDR[19]
  weim.ADDR[20]
  weim.ADDR[21]
  weim.ADDR[22]
  weim.ADDR[23]
  weim.ADDR[24]
  weim.CS0_B
  weim.OE
  weim.RW
  weim.LBA_B
  weim.AD[0]
  weim.AD[1]
  weim.AD[2]
  weim.AD[3]
  weim.AD[4]
  weim.AD[5]
  weim.AD[6]
  weim.AD[7]
- gpio5.IO[10]
  gpio5.IO[11]
  gpio5.IO[0]
  gpio5.IO[1]
  gpio5.IO[2]
  gpio5.IO[3]
  gpio5.IO[4]
  gpio5.IO[5]
  gpio5.IO[6]
  gpio5.IO[7]
  gpio5.IO[8]
  gpio5.IO[9]
  gpio1.IO[10]
  gpio1.IO[11]
  gpio1.IO[12]
  gpio1.IO[13]
  gpio1.IO[14]
  gpio1.IO[15]
  gpio1.IO[0]
  gpio1.IO[1]
  gpio1.IO[2]
  gpio1.IO[3]
  gpio1.IO[4]
  gpio1.IO[5]
  gpio1.IO[6]
  gpio1.IO[7]
  gpio1.IO[8]
  gpio1.IO[9]
  gpio1.IO[16]
  gpio1.IO[17]
  gpio1.IO[18]
  gpio1.IO[19]
  gpio1.IO[20]
  gpio1.IO[21]
  gpio1.IO[22]
  gpio1.IO[23]
  gpio1.IO[24]
  gpio1.IO[25]
  gpio1.IO[26]
  gpio1.IO[27]
  gpio1.IO[28]
  gpio1.IO[29]
  gpio1.IO[30]
  gpio1.IO[31]
  gpio2.IO[0]
  gpio2.IO[1]
  gpio2.IO[2]
  gpio2.IO[3]
  gpio2.IO[4]
  gpio2.IO[5]
  gpio2.IO[6]
  gpio2.IO[7]
  gpio2.IO[8]
  gpio2.IO[9]
  gpio2.IO[10]
  gpio2.IO[11]
  gpio2.IO[12]
  gpio2.IO[13]
  gpio2.IO[14]
  gpio2.IO[15]
  gpio3.IO[0]
  gpio3.IO[1]
  gpio3.IO[2]
  gpio3.IO[3]
  gpio3.IO[4]
  gpio3.IO[5]
  gpio3.IO[6]
  gpio3.IO[7]
  gpio3.IO[8]
  gpio3.IO[9]
  gpio3.IO[10]
  gpio3.IO[11]
  gpio3.IO[12]
  gpio3.IO[13]
  gpio3.IO[14]
  gpio3.IO[15]
  gpio3.IO[16]
  gpio3.IO[17]
  gpio3.IO[18]
  gpio3.IO[19]
  gpio3.IO[20]
  gpio3.IO[21]
  gpio3.IO[22]
  gpio3.IO[23]
  gpio3.IO[24]
  gpio3.IO[25]
  gpio3.IO[26]
  gpio3.IO[27]
  gpio3.IO[28]
  gpio4.IO[0]
  gpio4.IO[1]
  gpio4.IO[2]
  gpio4.IO[3]
  gpio4.IO[4]
  gpio4.IO[5]
  gpio4.IO[6]
  gpio4.IO[7]
  gpio4.IO[8]
  gpio4.IO[9]
  gpio4.IO[10]
  gpio4.IO[11]
  gpio4.IO[12]
  gpio4.IO[13]
  gpio4.IO[14]
  gpio4.IO[15]
  gpio4.IO[16]
  gpio2.IO[16]
  gpio2.IO[17]
  gpio2.IO[18]
  gpio2.IO[19]
  gpio2.IO[20]
  gpio2.IO[21]
  gpio4.IO[17]
  gpio4.IO[18]
  gpio4.IO[19]
  gpio4.IO[20]
  gpio4.IO[21]
  gpio4.IO[22]
  gpio4.IO[23]
  gpio4.IO[24]
  gpio4.IO[25]
  gpio4.IO[26]
  gpio4.IO[27]
  gpio4.IO[28]
- sdma.EXT_EVENT[0]
  sdma.EXT_EVENT[1]
  mqs.RIGHT
  mqs.LEFT
  osc32k.32K_OUT
  anatop.24M_OUT
  enet1.1588_EVENT0_IN
  enet1.1588_EVENT0_OUT
  sdma.EXT_EVENT[0]
  ccm.DI0_EXT_CLK
  enet2.1588_EVENT0_IN
  enet2.1588_EVENT0_OUT
  ccm.WAIT
  ccm.STOP
  ccm.PMIC_RDY
  usdhc1.RESET_B
  anatop.USBPHY1_TSTI_TX_LS_MODE
  anatop.USBPHY1_TSTI_TX_HS_MODE
  anatop.USBPHY1_TSTI_TX_DN
  anatop.USBPHY1_TSTO_RX_SQUELCH
  anatop.USBPHY1_TSTO_RX_DISCON_DET
  anatop.USBPHY1_TSTO_RX_HS_RXD
  anatop.USBPHY2_TSTO_RX_FS_RXD
  anatop.USBPHY1_TSTO_RX_FS_RXD
  anatop.USBPHY1_TSTI_TX_DP
  anatop.USBPHY1_TSTI_TX_EN
  anatop.USBPHY1_TSTI_TX_HIZ
  anatop.USBPHY2_TSTO_RX_HS_RXD
  anatop.USBPHY1_TSTO_PLL_CLK20DIV
  anatop.USBPHY2_TSTO_PLL_CLK20DIV
  anatop.USBPHY2_TSTO_RX_SQUELCH
  anatop.USBPHY2_TSTO_RX_DISCON_DET
  kpp.ROW[0]
  kpp.COL[0]
  kpp.ROW[1]
  kpp.COL[1]
  kpp.ROW[2]
  kpp.COL[2]
  kpp.ROW[3]
  kpp.COL[3]
  kpp.ROW[4]
  kpp.COL[4]
  kpp.ROW[5]
  kpp.COL[5]
  kpp.ROW[6]
  kpp.COL[6]
  kpp.ROW[7]
  kpp.COL[7]
  ocotp_ctrl_wrapper.FUSE_LATCHED
  anatop.TESTI[0]
  anatop.TESTI[1]
  anatop.TESTI[2]
  anatop.TESTI[3]
  src.BT_CFG[0]
  src.BT_CFG[1]
  src.BT_CFG[2]
  src.BT_CFG[3]
  src.BT_CFG[4]
  src.BT_CFG[5]
  src.BT_CFG[6]
  src.BT_CFG[7]
  src.BT_CFG[8]
  src.BT_CFG[9]
  src.BT_CFG[10]
  src.BT_CFG[11]
  src.BT_CFG[12]
  src.BT_CFG[13]
  src.BT_CFG[14]
  src.BT_CFG[15]
  src.BT_CFG[24]
  src.BT_CFG[25]
  src.BT_CFG[26]
  src.BT_CFG[27]
  src.BT_CFG[28]
  src.BT_CFG[29]
  src.BT_CFG[30]
  src.BT_CFG[31]
  anatop.TESTO[0]
  anatop.TESTO[1]
  anatop.TESTO[2]
  anatop.TESTO[3]
  anatop.TESTO[4]
  anatop.TESTO[5]
  anatop.TESTO[6]
  anatop.TESTO[7]
  anatop.TESTO[8]
  anatop.TESTO[9]
  anatop.TESTO[10]
  anatop.TESTO[11]
  anatop.TESTO[12]
  anatop.TESTO[13]
  anatop.TESTO[14]
  anatop.TESTO[15]
  sdma.EXT_EVENT[1]
  sdma.EXT_EVENT[0]
  ccm.OUT0
  ccm.OUT1
  ccm.OUT2
  ccm.CLKO1
  ccm.CLKO2
  snvs_hp_wrapper.VIO_5_CTL
  snvs_hp_wrapper.VIO_5
  pwm7.OUT
  pwm8.OUT
  src.INT_BOOT
  sai1.MCLK
  sai1.RX_SYNC
  sai1.RX_BCLK
  sai1.TX_SYNC
  sai1.TX_BCLK
  sai1.RX_DATA
  sai1.TX_DATA
- src.SYSTEM_RESET
  src.EARLY_RESET
  src.ANY_PU_RESET
  src.TESTER_ACK
  ccm.PLL2_BYP
  ccm.PLL3_BYP
  ccm.REF_EN_B
  ecspi1.TESTER_TRIGGER
  ecspi2.TESTER_TRIGGER
  ecspi3.TESTER_TRIGGER
  ecspi4.TESTER_TRIGGER
  usdhc1.TESTER_TRIGGER
  usdhc2.TESTER_TRIGGER
  qspi.TESTER_TRIGGER
  rawnand.TESTER_TRIGGER
  sjc.DONE
  sjc.DE_B
  sjc.FAIL
  sjc.JTAG_ACT
  sim_m.HADDR[0]
  sim_m.HADDR[1]
  sim_m.HADDR[2]
  sim_m.HADDR[3]
  sim_m.HADDR[4]
  sim_m.HADDR[5]
  sim_m.HADDR[6]
  sim_m.HADDR[7]
  sim_m.HADDR[8]
  sim_m.HADDR[9]
  sim_m.HADDR[10]
  sim_m.HADDR[11]
  sim_m.HADDR[12]
  sim_m.HADDR[13]
  sim_m.HADDR[14]
  sim_m.HADDR[15]
  sim_m.HADDR[16]
  sim_m.HADDR[17]
  sim_m.HADDR[18]
  sim_m.HADDR[19]
  sim_m.HADDR[20]
  sim_m.HADDR[21]
  sim_m.HADDR[22]
  sim_m.HADDR[23]
  sim_m.HADDR[24]
  sim_m.HADDR[25]
  sim_m.HADDR[26]
  sim_m.HADDR[27]
  sim_m.HADDR[28]
  sim_m.HADDR[29]
  sim_m.HADDR[30]
  sim_m.HADDR[31]
  sim_m.HBURST[0]
  sim_m.HBURST[1]
  sim_m.HBURST[2]
  sim_m.HMASTLOCK
  sim_m.HPROT[0]
  sim_m.HPROT[1]
  sim_m.HPROT[2]
  sim_m.HPROT[3]
  sim_m.HREADYOUT
  sim_m.HRESP
  sim_m.HSIZE[0]
  sim_m.HSIZE[1]
  sim_m.HSIZE[2]
  sim_m.HWRITE
  tpsmp.CLK
  tpsmp.HDATA_DIR
  tpsmp.HTRANS[0]
  tpsmp.HTRANS[1]
  tpsmp.HDATA[0]
  tpsmp.HDATA[1]
  tpsmp.HDATA[2]
  tpsmp.HDATA[3]
  tpsmp.HDATA[4]
  tpsmp.HDATA[5]
  tpsmp.HDATA[6]
  tpsmp.HDATA[7]
  tpsmp.HDATA[8]
  tpsmp.HDATA[9]
  tpsmp.HDATA[10]
  tpsmp.HDATA[11]
  tpsmp.HDATA[12]
  tpsmp.HDATA[13]
  tpsmp.HDATA[14]
  tpsmp.HDATA[15]
  tpsmp.HDATA[16]
  tpsmp.HDATA[19]
  tpsmp.HDATA[17]
  tpsmp.HDATA[18]
  observe_mux.OUT[0]
  observe_mux.OUT[1]
  observe_mux.OUT[2]
  observe_mux.OUT[3]
  observe_mux.OUT[4]
  tpsmp.HDATA[20]
  tpsmp.HDATA[21]
  tpsmp.HDATA[22]
  tpsmp.HDATA[23]
  tpsmp.HDATA[24]
  tpsmp.HDATA[25]
  tpsmp.HDATA[26]
  tpsmp.HDATA[27]
  tpsmp.HDATA[28]
  tpsmp.HDATA[29]
  tpsmp.HDATA[30]
  tpsmp.HDATA[31]
- epit1.OUT
  epit2.OUT
  wdog3.WDOG_B
  wdog1.WDOG_B
  uart1.TX
  uart1.RX
  uart5.TX
  uart5.RX
  uart1.CTS_B
  uart1.RTS_B
  uart5.RTS_B
  uart5.CTS_B
  spdif.OUT
  spdif.IN
  usdhc2.WP
  usdhc2.CD_B
  ecspi3.SS0
  ecspi3.SCLK
  ecspi3.MOSI
  ecspi3.MISO
  anatop.OTG1_ID
  epit1.OUT
  epit2.OUT
  wdog1.WDOG_B
  ecspi2.SCLK
  ecspi2.SS0
  ecspi2.MOSI
  ecspi2.MISO
  usdhc1.LCTL
  usdhc2.LCTL
  usdhc1.VSELECT
  usdhc2.VSELECT
  wdog1.WDOG_RST_B_DEB
  wdog2.WDOG_RST_B_DEB
  gpt1.CLK
  gpt1.CAPTURE2
  usb.OTG1_PWR
  usb.OTG1_OC
  anatop.ENET_REF_CLK_25M
  anatop.24M_OUT
  usb.OTG2_PWR
  usb.OTG2_OC
  anatop.OTG2_ID
  global wdog
  wdog1.WDOG_RST_B_DEB
  ecspi2.RDY
  ecspi2.SS1
  ecspi2.SS2
  ecspi2.SS3
  sai1.MCLK
  sai1.TX_SYNC
  sai1.TX_BCLK
  sai1.RX_DATA
  sai1.TX_DATA
  ecspi1.SS1
  ecspi1.SS2
  ecspi1.SS3
  can1.TX
  can1.RX
  can2.TX
  can2.RX
  ecspi1.RDY
  usdhc2.RESET_B
  usdhc2.DATA4
  usdhc2.DATA5
  usdhc2.DATA6
  usdhc2.DATA7
  usdhc2.CMD
  usdhc2.CLK
  usdhc2.DATA0
  usdhc2.DATA1
  usdhc2.DATA2
  usdhc2.DATA3
  ecspi3.SS2
  ecspi3.SS3
  ecspi4.RDY
  ecspi4.SS1
  ecspi4.SS2
  ecspi4.SS3
  uart2.TX
  uart2.RX
  uart2.CTS_B
  uart2.RTS_B
  ecspi3.SS1
  ecspi3.RDY
  uart3.TX
  uart3.RX
  uart3.CTS_B
  uart3.RTS_B
  spdif.EXT_CLK
  usb.OTG1_PWR
  usb.OTG1_OC
  anatop.OTG1_ID
  usb.OTG2_PWR
  usb.OTG2_OC
  anatop.OTG2_ID
  uart6.TX
  uart6.RX
  uart6.RTS_B
  uart6.CTS_B
  uart5.TX
  uart5.RX
  uart5.RTS_B
  uart5.CTS_B
  usdhc1.WP
  usdhc1.CD_B
  usdhc1.RESET_B
  usdhc1.VSELECT
- uart5.TX
  uart5.RX
  uart5.CTS_B
  uart5.RTS_B
  epdc.PWRCTRL[1]
  epdc.PWRCTRL[2]
  epdc.PWRCTRL[3]
  epdc.SDCE[4]
  epdc.SDCE[5]
  epdc.SDCE[6]
  epdc.SDCE[7]
  epdc.SDCE[8]
  epdc.SDCE[9]
  epdc.SDOED
  epdc.SDOEZ
  epdc.SDDO[8]
  epdc.SDDO[9]
  epdc.SDDO[10]
  epdc.SDDO[11]
  epdc.SDDO[12]
  epdc.SDDO[13]
  epdc.SDDO[14]
  epdc.SDDO[15]
  epdc.SDCLK
  epdc.SDLE
  epdc.SDOE
  epdc.SDCE[0]
  epdc.GDOE
  epdc.SDDO[0]
  epdc.SDDO[1]
  epdc.SDDO[2]
  epdc.SDDO[3]
  epdc.SDDO[4]
  epdc.SDDO[5]
  epdc.SDDO[6]
  epdc.SDDO[7]
  epdc.PWRIRQ
  epdc.PWRWAKE
  epdc.PWRCOM
  epdc.PWRSTAT
  epdc.PWRCTRL[0]
  epdc.BDR[0]
  epdc.SDSHR
  epdc.GDRL
  epdc.GDCLK
  epdc.GDSP
  epdc.BDR[1]
  epdc.VCOM[0]
  epdc.VCOM[1]
  epdc.SDCE[1]
  epdc.SDCE[2]
  epdc.SDCE[3]
  esai.TX3_RX2
  esai.TX2_RX3
  esai.TX4_RX1
  esai.TX1
  esai.TX_HF_CLK
  esai.RX_HF_CLK
  esai.RX_FS
  esai.RX_CLK
  esai.TX_FS
  esai.TX_CLK
  esai.TX5_RX0
  esai.TX0
- 100K PD
  100K PU
  100K PU
  100K PU
  100K PD
  100K PD
  100K PD
  Keeper
  Keeper
  Keeper
  Keeper
  Keeper
  Keeper
  Keeper
  Keeper
  Keeper
  Keeper
  100K PU
  47K PU
  100K PU
  47K PU
  47K PU
  47K PU
  Keeper
  Keeper
  Keeper
  Keeper
  Keeper
  Keeper
  Keeper
  Keeper
  Keeper
  Keeper
  Keeper
  Keeper
  Keeper
  Keeper
  Keeper
  Keeper
  Keeper
  Keeper
  Keeper
  Keeper
  Keeper
  Keeper
  Keeper
  Keeper
  Keeper
  Keeper
  Keeper
  Keeper
  Keeper
  Keeper
  Keeper
  Keeper
  Keeper
  Keeper
  Keeper
  Keeper
  Keeper
  Keeper
  Keeper
  Keeper
  Keeper
  Keeper
  Keeper
  Keeper
  Keeper
  Keeper
  Keeper
  Keeper
  Keeper
  Keeper
  Keeper
  Keeper
  Keeper
  Keeper
  Keeper
  Keeper
  Keeper
  Keeper
  Keeper
  Keeper
  Keeper
  Keeper
  Keeper
  Keeper
  Keeper
  Keeper
  Keeper
  Keeper
  Keeper
  Keeper
  Keeper
  Keeper
  Keeper
  Keeper
  Keeper
  Keeper
  Keeper
  Keeper
  Keeper
  Keeper
  Keeper
  Keeper
  Keeper
  Keeper
  Keeper
  Keeper
  Keeper
  Keeper
  Keeper
  Keeper
  Keeper
  Keeper
  Keeper
  Keeper
  Keeper
  Keeper
  Keeper
  Keeper
  Keeper
  Keeper
  Keeper
  Keeper
  Keeper
  Keeper
  Keeper
  Keeper
sheet 13
- eMMC Storage <4.51>
- NAND FLASH
- # Option 1
- # Option 2
- # Stitching CAP for Layout
- # Flash Type:  MLC
- eMMC: MTFC8GACAAAM-1M WT
- 20nm: MT29F32G08CBADBWP-12IT:D
  25nm: MT29F32G08CBACAWP-Z:C
- Hinge Type MicroSD
- # Option 3
- # Hinge TYPE
- QSPI
- # Option 2
